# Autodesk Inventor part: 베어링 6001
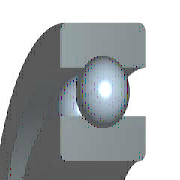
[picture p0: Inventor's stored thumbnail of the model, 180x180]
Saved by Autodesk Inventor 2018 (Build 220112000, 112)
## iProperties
Created: 2012-02
Part Number: 베어링 6001
Material: 강철, 연강
Description: 깊은 그루브 볼 베어링
Document SubType Name: Modeling
Standard: KS B 2023
Designer: mduedu
Standards Organization: KS
Language: ko-KR
Size Designation: 6001 - 12 x 28 x 8
Categories: <MemberInstance><Categories><Category DisplayName="샤프트 부품" InternalName="7f7aeb1f-a693-4053-b835-cee3144e0d98" Mnemonic="SHFT"><Category DisplayName="베어링" Inter
Density: 7.86 g/cm^3
Mass: 21.4855 g
Surface Area: 31.1809 cm^2
Volume: 2.73352 cm^3
Appearance: 노란색
IsCustomPart: 1
Author: mduedu
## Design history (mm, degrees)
sketch "스케치" dims "d0" = 4.16 (= -0.26 x WD + 0.26 x BD)
  geometry: L1 (1.92, 10)-(6.08, 10); L2 (4, 10)-(4, 7.92); L3 (4, 10)-(4, 12.08); L4 (2.454, 8.608)-(0, 8.608); L5 (0, 6)-(8, 6); L6 (2.454, 11.392)-(0, 11.392); L7 (0, 14)-(8, 14); L8 (8, 6)-(8, 8.608); L9 (5.546, 8.608)-(8, 8.608); L10 (5.546, 11.392)-(8, 11.392); L11 (8, 14)-(8, 11.392); L12 (-1.4, 0)-(8.4, 0) reference; L13 (0, -0.3)-(0, 5.3) reference
  constraints: 22 end point, 4 point on line, 2 collinear, 2 perpendicular, 2 symmetric about line, 1 midpoint, 1 parallel, 14 other
  dimensions: "d9" = 12 diameter of L5 L12 (= WD); "d11" = 28 diameter of L7 L12 (= BD); "d12" = 8 distance between parallel lines of L8 L13 (= KB); "d13" = 17.216 diameter of L9 L12 (= 0.326 x BD + 0.674 x WD)
revolve "본체" stored, may be unused: angle "d6" = 90 deg
revolve "볼" stored, may be unused: angle "d7" = 90 deg
pattern_circular "IDS_ARRAYBALL[SIMPL:T]" dims angle "d3" = 360 deg
body "Solid1"
fillet "모깎기1" dims "d1" = 0.3 (= KRS)
other parameters: "WD" = 12 [user parameter; used in 5 equation terms], "BD" = 28 [user parameter; used in 5 equation terms], "KB" = 8 [user parameter; used in 1 equation term], "KRS" = 0.3 [user parameter; used in 1 equation term], "d4" = 0, "d5" = 0, "d8" = 0, "d14" = 0, "d15" = 0, "BBA" = 0 [user parameter], "BC0" = 2360000 [user parameter], "BC" = 5070000 [user parameter], "BR" = 14 (= 0.5 x BD) [user parameter], "WR" = 6 (= 0.5 x WD) [user parameter]
